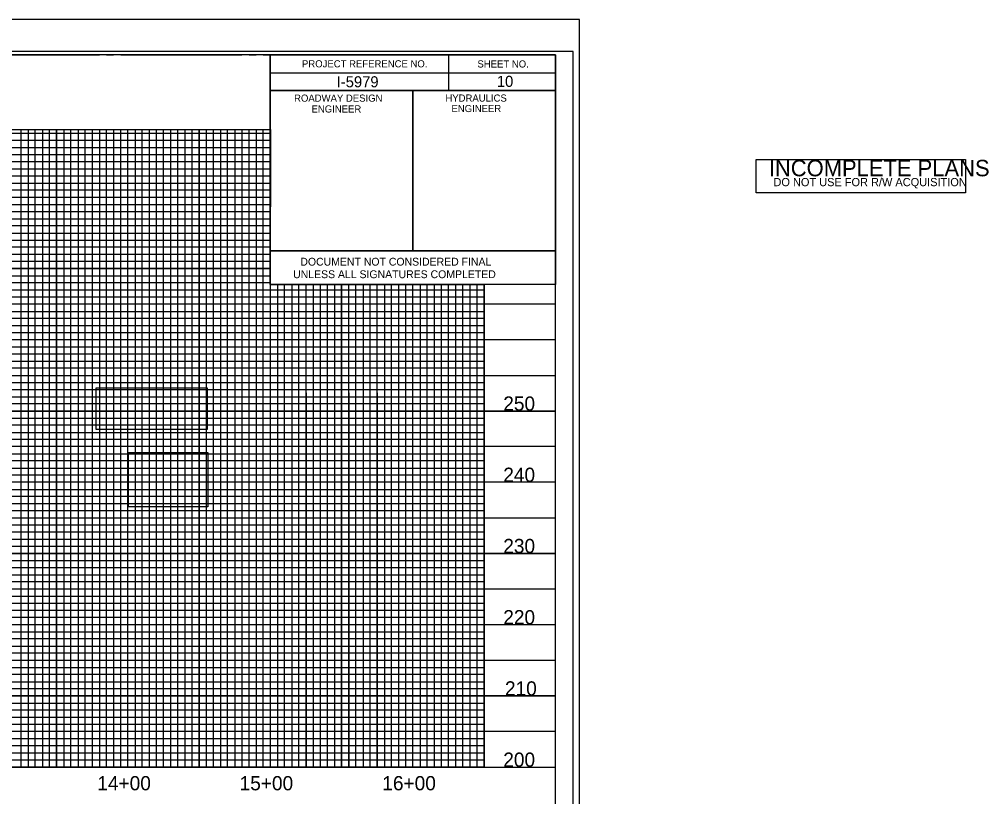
# Model space of a CAD drawing. Extents: x 1810963 to 1812934, y 722070 to 723170.
# Drawn here: x 1812254 to 1812934, y 722624 to 723170 of the extents above; entities that cross this region are included whole.
import ezdxf

# ---------------------------------------------------------------- set-up
doc = ezdxf.new("R2010")
doc.units = 0
for name, color, linetype in [('Old_Level_11', 7, 'Continuous'), ('Old_Level_2', 7, 'Continuous'), ('Prop Conc 2ft 6in Curb and Gutter', 7, 'Continuous'), ('Prop Dimension Text', 7, 'Continuous'), ('Prop Grid Mask', 7, 'Continuous'), ('Prop Horizontal Alignment Station Label', 7, 'Continuous'), ('Prop RDY Traffic Signal CELL', 7, 'Continuous'), ('Prop Shade Heavy', 7, 'Continuous'), ('Prop Shade Light', 7, 'Continuous'), ('Scratch_Level_0', 7, 'Continuous'), ('Scratch_Level_3', 7, 'Continuous'), ('Scratch_Level_5', 7, 'Continuous'), ('Sheet Block Title CELL', 7, 'Continuous'), ('Sheet North Arrow CELL', 7, 'Continuous'), ('Sheet Symbology CELL', 7, 'Continuous'), ('Sheet Title CELL', 7, 'Continuous')]:
    doc.layers.add(name, color=color, linetype=linetype)

msp = doc.modelspace()

# ---------------------------------------------------------------- linework, layer by layer
at = {"layer": 'Old_Level_11'}
msp.add_lwpolyline([(1810976.46, 722092.33), (1812642.96, 722092.33), (1812642.96, 723147.43), (1810976.46, 723147.43)], close=True, dxfattribs=at)
at = {"layer": 'Old_Level_2'}
for points in [[(1812308.11, 722911.09), (1812386.08, 722911.09), (1812386.08, 722881.84), (1812308.11, 722881.84)], [(1812330.97, 722865.77), (1812386.54, 722865.77), (1812386.54, 722827.65), (1812330.97, 722827.65)]]:
    msp.add_lwpolyline(points, close=True, dxfattribs=at)
at = {"layer": 'Prop Conc 2ft 6in Curb and Gutter'}
for p, q in [((1812280.46, 722644.88), (1812280.46, 723092.45)), ((1812330.46, 722644.88), (1812330.46, 723092.45)), ((1812380.46, 722644.88), (1812380.46, 723092.45)), ((1812430.41, 723044.88), (1811130.46, 723044.88)), ((1812430.46, 722644.88), (1812430.46, 723007.33)), ((1812430.46, 722994.88), (1811130.46, 722994.88)), ((1812480.46, 722644.88), (1812480.46, 722983.83)), ((1812530.46, 722644.88), (1812530.46, 722983.83)), ((1812580.46, 722644.88), (1812580.46, 722983.83)), ((1812630.46, 722944.88), (1811130.46, 722944.88)), ((1812630.46, 722894.88), (1811130.46, 722894.88)), ((1812630.46, 722844.88), (1811130.46, 722844.88)), ((1812630.46, 722794.88), (1811130.46, 722794.88)), ((1812630.46, 722744.88), (1811130.46, 722744.88)), ((1812630.46, 722694.88), (1811130.46, 722694.88))]:
    msp.add_line(p, q, dxfattribs=at)
at = {"layer": 'Prop Dimension Text'}
for p, q in [((1812430.41, 722983.83), (1812430.41, 723007.33)), ((1812430.41, 723007.33), (1812630.45, 723007.33)), ((1812430.41, 722983.83), (1812430.41, 723007.33)), ((1812430.41, 723007.33), (1812630.45, 723007.33)), ((1812630.45, 723007.32), (1812630.45, 722983.82)), ((1812630.45, 723007.32), (1812630.45, 722983.82)), ((1812630.45, 722983.83), (1812430.41, 722983.83)), ((1812630.45, 722983.83), (1812430.41, 722983.83))]:
    msp.add_line(p, q, dxfattribs=at)
at = {"layer": 'Prop Horizontal Alignment Station Label'}
msp.add_lwpolyline([(1812771.3, 723048.01), (1812771.3, 723071.51), (1812918.3, 723071.51), (1812918.3, 723048.01)], close=True, dxfattribs=at)
at = {"layer": 'Prop RDY Traffic Signal CELL'}
msp.add_line((1812647.46, 723169.88), (1810963.46, 723169.88), dxfattribs=at)
at = {"layer": 'Prop Shade Heavy'}
for points in [[(1812230.46, 723144.88), (1812280.46, 723144.88)], [(1812330.46, 723144.88), (1812380.46, 723144.88)], [(1812380.46, 723092.45), (1812380.46, 722644.88), (1812430.46, 722644.88), (1812430.46, 723144.88), (1812456.76, 723144.88)], [(1812280.46, 723092.45), (1812280.46, 722644.88), (1812330.46, 722644.88), (1812330.46, 723092.45)], [(1812430.46, 723044.88), (1811130.46, 723044.88), (1811130.46, 722994.88), (1812430.46, 722994.88)], [(1812580.46, 722983.83), (1812580.46, 722644.88), (1812630.46, 722644.88), (1812630.46, 722994.88)], [(1812480.46, 722983.83), (1812480.46, 722644.88), (1812530.46, 722644.88), (1812530.46, 722644.88), (1812530.46, 722983.83)], [(1812630.46, 722944.88), (1811130.46, 722944.88), (1811130.46, 722894.88), (1812630.46, 722894.88)], [(1812630.46, 722844.88), (1811130.46, 722844.88), (1811130.46, 722794.88), (1812630.46, 722794.88)], [(1812630.46, 722744.88), (1811130.46, 722744.88), (1811130.46, 722744.88), (1811130.46, 722694.88), (1812630.46, 722694.88)]]:
    msp.add_lwpolyline(points, dxfattribs=at)
at = {"layer": 'Prop Shade Light'}
for p, q in [((1812255.46, 723144.88), (1812305.46, 723144.88)), ((1812355.46, 723144.88), (1812405.46, 723144.88)), ((1812255.46, 722644.88), (1812255.46, 723092.45)), ((1812305.46, 723092.45), (1812305.46, 722644.88)), ((1812355.46, 722644.88), (1812355.46, 723092.45)), ((1812405.46, 723092.45), (1812405.46, 722644.88)), ((1812455.46, 722644.88), (1812455.46, 722983.83)), ((1812205.46, 722644.88), (1812255.46, 722644.88)), ((1812305.46, 722644.88), (1812355.46, 722644.88)), ((1812405.46, 722644.88), (1812455.46, 722644.88))]:
    msp.add_line(p, q, dxfattribs=at)
for points in [[(1812430.46, 723069.88), (1811130.46, 723069.88), (1811130.46, 723019.88), (1812430.46, 723019.88)], [(1812455.46, 722907.68), (1812455.46, 722644.88), (1812505.46, 722644.88), (1812505.46, 722983.83)], [(1812505.46, 722907.68), (1812505.46, 722644.88), (1812555.46, 722644.88), (1812555.46, 722983.83)], [(1812630.46, 722969.88), (1811130.46, 722969.88), (1811130.46, 722919.88), (1812455.46, 722919.88)], [(1812455.46, 722919.88), (1812630.46, 722919.88)], [(1812630.46, 722869.88), (1811130.46, 722869.88), (1811130.46, 722819.88), (1812630.46, 722819.88)], [(1812630.46, 722769.88), (1811130.46, 722769.88), (1811130.46, 722719.88), (1812630.46, 722719.88)], [(1812630.46, 722669.88), (1811130.46, 722669.88)]]:
    msp.add_lwpolyline(points, dxfattribs=at)
at = {"layer": 'Scratch_Level_3'}
msp.add_lwpolyline([(1811180.46, 723144.88), (1812230.46, 723144.88), (1812230.46, 723092.45), (1812430.5, 723092.45), (1812430.41, 722983.83), (1812580.46, 722983.83), (1812580.46, 722644.88), (1811180.46, 722644.88)], close=True, dxfattribs=at)
at = {"layer": 'Scratch_Level_5'}
msp.add_lwpolyline([(1811180.46, 722983.83), (1811180.46, 722644.88), (1812580.46, 722644.88), (1812580.46, 722983.83)], dxfattribs=at)
at = {"layer": 'Sheet North Arrow CELL'}
msp.add_lwpolyline([(1810963.46, 722069.88), (1812647.46, 722069.88), (1812647.46, 723169.88), (1810963.46, 723169.88)], close=True, dxfattribs=at)
at = {"layer": 'Sheet Symbology CELL'}
for p, q in [((1812555.46, 723144.83), (1812555.46, 723119.83)), ((1812430.41, 723132.33), (1812630.46, 723132.33)), ((1812530.46, 723119.83), (1812530.46, 723007.38)), ((1811130.46, 722644.88), (1812630.46, 722644.88))]:
    msp.add_line(p, q, dxfattribs=at)
for points in [[(1812630.46, 723144.88), (1811130.46, 723144.88), (1811130.46, 722094.88), (1812630.46, 722094.88)], [(1812430.41, 723144.88), (1812630.46, 723144.88), (1812630.46, 723119.83), (1812430.41, 723119.83)], [(1812430.41, 723119.83), (1812530.46, 723119.83), (1812530.46, 723007.33), (1812430.41, 723007.33)], [(1812530.46, 723119.83), (1812630.46, 723119.83), (1812630.46, 723007.33), (1812530.46, 723007.33)]]:
    msp.add_lwpolyline(points, close=True, dxfattribs=at)
at = {"layer": 'Sheet Title CELL'}
for p, q in [((1812250.46, 723144.88), (1812260.46, 723144.88)), ((1812265.46, 723144.88), (1812270.46, 723144.88)), ((1812275.46, 723144.88), (1812285.46, 723144.88)), ((1812290.46, 723144.88), (1812295.46, 723144.88)), ((1812300.46, 723144.88), (1812310.46, 723144.88)), ((1812315.46, 723144.88), (1812320.46, 723144.88)), ((1811180.46, 723089.88), (1812430.46, 723089.88)), ((1812260.46, 723092.45), (1812260.46, 722644.88)), ((1812265.46, 722644.88), (1812265.46, 723092.45)), ((1812270.46, 723092.45), (1812270.46, 722644.88)), ((1812275.46, 722644.88), (1812275.46, 723092.45)), ((1812285.46, 723092.45), (1812285.46, 722644.88)), ((1812290.46, 722644.88), (1812290.46, 723092.45)), ((1812295.46, 723092.45), (1812295.46, 722644.88)), ((1812300.46, 722644.88), (1812300.46, 723092.45)), ((1812310.46, 723092.45), (1812310.46, 722644.88)), ((1812315.46, 722644.88), (1812315.46, 723092.45)), ((1812320.46, 723092.45), (1812320.46, 722644.88)), ((1812430.41, 723009.88), (1811180.46, 723009.88)), ((1812430.46, 723004.88), (1811180.46, 723004.88)), ((1812430.46, 722999.88), (1811180.46, 722999.88)), ((1811180.46, 722989.88), (1812430.46, 722989.88)), ((1812430.46, 722984.88), (1811180.46, 722984.88)), ((1811180.46, 722979.88), (1812580.46, 722979.88)), ((1812580.46, 722959.88), (1811180.46, 722959.88)), ((1811180.46, 722954.88), (1812580.46, 722954.88)), ((1812580.46, 722934.88), (1811180.46, 722934.88)), ((1811180.46, 722929.88), (1812580.46, 722929.88)), ((1812580.46, 722909.88), (1811180.46, 722909.88)), ((1811180.46, 722904.88), (1812580.46, 722904.88)), ((1812580.46, 722899.88), (1811180.46, 722899.88)), ((1811180.46, 722889.88), (1812580.46, 722889.88)), ((1812580.46, 722884.88), (1811180.46, 722884.88)), ((1811180.46, 722879.88), (1812580.46, 722879.88)), ((1812580.46, 722874.88), (1811180.46, 722874.88)), ((1811180.46, 722864.88), (1812580.46, 722864.88)), ((1812580.46, 722859.88), (1811180.46, 722859.88)), ((1811180.46, 722854.88), (1812580.46, 722854.88)), ((1812580.46, 722849.88), (1811180.46, 722849.88)), ((1811180.46, 722839.88), (1812580.46, 722839.88)), ((1812580.46, 722834.88), (1811180.46, 722834.88)), ((1811180.46, 722829.88), (1812580.46, 722829.88)), ((1812580.46, 722824.88), (1811180.46, 722824.88)), ((1811180.46, 722814.88), (1812580.46, 722814.88)), ((1812580.46, 722809.88), (1811180.46, 722809.88)), ((1811180.46, 722804.88), (1812580.46, 722804.88)), ((1812580.46, 722799.88), (1811180.46, 722799.88)), ((1811180.46, 722789.88), (1812580.46, 722789.88)), ((1812580.46, 722784.88), (1811180.46, 722784.88)), ((1811180.46, 722779.88), (1812580.46, 722779.88)), ((1812580.46, 722774.88), (1811180.46, 722774.88)), ((1811180.46, 722764.88), (1812580.46, 722764.88)), ((1812580.46, 722759.88), (1811180.46, 722759.88)), ((1812580.46, 722754.88), (1811180.46, 722754.88)), ((1812580.46, 722749.88), (1811180.46, 722749.88)), ((1811180.46, 722739.88), (1812580.46, 722739.88)), ((1812580.46, 722734.88), (1811180.46, 722734.88)), ((1811180.46, 722729.88), (1812580.46, 722729.88)), ((1812580.46, 722724.88), (1811180.46, 722724.88)), ((1811180.46, 722714.88), (1812580.46, 722714.88)), ((1812580.46, 722709.88), (1811180.46, 722709.88)), ((1811180.46, 722704.88), (1812580.46, 722704.88)), ((1812580.46, 722699.88), (1811180.46, 722699.88)), ((1811180.46, 722689.88), (1812580.46, 722689.88)), ((1812580.46, 722684.88), (1811180.46, 722684.88)), ((1811180.46, 722679.88), (1812580.46, 722679.88)), ((1812580.46, 722674.88), (1811180.46, 722674.88)), ((1811180.46, 722664.88), (1812580.46, 722664.88)), ((1812580.46, 722659.88), (1811180.46, 722659.88)), ((1811180.46, 722654.88), (1812580.46, 722654.88)), ((1812260.46, 722644.88), (1812265.46, 722644.88)), ((1812270.46, 722644.88), (1812275.46, 722644.88)), ((1812285.46, 722644.88), (1812290.46, 722644.88)), ((1812295.46, 722644.88), (1812300.46, 722644.88)), ((1812310.46, 722644.88), (1812315.46, 722644.88))]:
    msp.add_line(p, q, dxfattribs=at)
for points in [[(1812325.46, 723144.88), (1812335.46, 723144.88)], [(1812340.46, 723144.88), (1812345.46, 723144.88)], [(1812350.46, 723144.88), (1812360.46, 723144.88)], [(1812365.46, 723144.88), (1812370.46, 723144.88)], [(1812375.46, 723144.88), (1812385.46, 723144.88)], [(1812390.46, 723144.88), (1812395.46, 723144.88)], [(1812400.46, 723144.88), (1812410.46, 723144.88)], [(1812415.46, 723144.88), (1812420.46, 723144.88)], [(1812425.46, 723144.88), (1812435.46, 723144.88)], [(1812320.46, 722644.88), (1812325.46, 722644.88), (1812325.46, 723092.45)], [(1812335.46, 723092.45), (1812335.46, 722644.88), (1812340.46, 722644.88), (1812340.46, 723092.45)], [(1812345.46, 723092.45), (1812345.46, 722644.88), (1812350.46, 722644.88), (1812350.46, 723092.45)], [(1812360.46, 723092.45), (1812360.46, 722644.88), (1812365.46, 722644.88), (1812365.46, 723092.45)], [(1812370.46, 723092.45), (1812370.46, 722644.88), (1812375.46, 722644.88), (1812375.46, 723092.45)], [(1812385.46, 723092.45), (1812385.46, 722644.88), (1812390.46, 722644.88), (1812390.46, 723092.45)], [(1812395.46, 723092.45), (1812395.46, 722644.88), (1812400.46, 722644.88), (1812400.46, 723092.45)], [(1812410.46, 723092.45), (1812410.46, 722644.88), (1812415.46, 722644.88), (1812415.46, 723092.45)], [(1812420.46, 723092.45), (1812420.46, 722644.88), (1812425.46, 722644.88), (1812425.46, 723092.45)], [(1812430.46, 723084.88), (1811180.46, 723084.88), (1811180.46, 723079.88), (1812430.46, 723079.88)], [(1812430.46, 723074.88), (1811180.46, 723074.88), (1811180.46, 723064.88), (1812430.46, 723064.88)], [(1812430.46, 723059.88), (1811180.46, 723059.88), (1811180.46, 723054.88), (1812430.46, 723054.88)], [(1812430.46, 723049.88), (1811180.46, 723049.88), (1811180.46, 723039.88), (1812430.46, 723039.88)], [(1812430.46, 723034.78), (1811180.56, 723034.78), (1811180.56, 723029.88), (1812430.46, 723029.88)], [(1812430.46, 723024.88), (1811180.46, 723024.88), (1811180.46, 723014.88), (1812430.46, 723014.88)], [(1812435.46, 722983.83), (1812435.46, 722644.88), (1812440.46, 722644.88), (1812440.46, 722983.83)], [(1812445.46, 722983.83), (1812445.46, 722644.88), (1812450.46, 722644.88), (1812450.46, 722983.83)], [(1812460.46, 722983.83), (1812460.46, 722644.88), (1812460.46, 722644.88), (1812465.46, 722644.88), (1812470.46, 722644.88), (1812470.46, 722983.83)], [(1812465.46, 722983.83), (1812465.46, 722644.88)], [(1812475.45, 722983.83), (1812475.36, 722644.93), (1812480.36, 722644.93), (1812485.46, 722644.88), (1812485.46, 722983.83)], [(1812485.46, 722907.68), (1812485.46, 722644.88), (1812490.46, 722644.88), (1812490.46, 722983.83)], [(1812495.46, 722983.83), (1812495.46, 722644.88), (1812500.46, 722644.88), (1812500.46, 722983.83)], [(1812510.46, 722983.83), (1812510.46, 722644.88), (1812515.46, 722644.88), (1812515.46, 722983.83)], [(1812520.46, 722983.83), (1812520.46, 722644.88), (1812525.46, 722644.88), (1812525.46, 722983.83)], [(1812535.46, 722983.83), (1812535.46, 722644.88), (1812540.46, 722644.88), (1812540.46, 722983.83)], [(1812545.46, 722983.83), (1812545.46, 722644.88), (1812550.46, 722644.88), (1812550.46, 722983.83)], [(1812560.46, 722983.83), (1812560.46, 722644.88), (1812565.46, 722644.88), (1812565.46, 722983.83)], [(1812570.46, 722983.83), (1812570.46, 722644.88), (1812575.46, 722644.88), (1812575.46, 722983.83)], [(1812580.46, 722974.88), (1811180.46, 722974.88), (1811180.46, 722964.88), (1812580.46, 722964.88)], [(1812580.46, 722949.88), (1811180.46, 722949.88), (1811180.46, 722939.88), (1812580.46, 722939.88)], [(1812580.46, 722924.88), (1811180.46, 722924.88), (1811180.46, 722914.88), (1812580.46, 722914.88)], [(1812580.46, 722649.88), (1811180.46, 722649.88)]]:
    msp.add_lwpolyline(points, dxfattribs=at)

# ---------------------------------------------------------------- texts
at = {"layer": 'Prop Dimension Text'}
for s, p in [('DOCUMENT NOT CONSIDERED FINAL', (1812451.48, 722996.99)), ('DOCUMENT NOT CONSIDERED FINAL', (1812451.48, 722996.99)), ('UNLESS ALL SIGNATURES COMPLETED', (1812446.41, 722988.19)), ('UNLESS ALL SIGNATURES COMPLETED', (1812446.41, 722988.19))]:
    msp.add_text(s, height=5.5, dxfattribs=at).set_placement(p)
at = {"layer": 'Prop Grid Mask'}
for s, p in [('I-5979', (1812476.99, 723122.19)), ('10', (1812589.38, 723122.49))]:
    msp.add_text(s, height=7.75, dxfattribs=at).set_placement(p)
at = {"layer": 'Prop Horizontal Alignment Station Label'}
for s, height, p in [('INCOMPLETE PLANS', 11.52, (1812780.25, 723059.71)), ('DO NOT USE FOR R/W ACQUISITION', 5.76, (1812783.5, 723052.76))]:
    msp.add_text(s, height=height, dxfattribs=at).set_placement(p)
at = {"layer": 'Scratch_Level_0'}
for s, p in [('250', (1812593.89, 722895.13)), ('240', (1812593.89, 722845.13)), ('230', (1812593.89, 722795.13)), ('220', (1812593.89, 722745.13)), ('210', (1812595.09, 722695.13)), ('200', (1812593.89, 722645.13))]:
    msp.add_text(s, height=10, dxfattribs=at).set_placement(p)
at = {"layer": 'Sheet Block Title CELL'}
for s, p in [('14+00', (1812309.01, 722628.6)), ('15+00', (1812408.88, 722628.6)), ('16+00', (1812509.01, 722628.6))]:
    msp.add_text(s, height=10, dxfattribs=at).set_placement(p)
at = {"layer": 'Sheet Symbology CELL'}
for s, height, p in [('PROJECT REFERENCE NO.', 5.0001, (1812452.62, 723136.19)), ('SHEET NO.', 5, (1812575.77, 723136.09)), ('ROADWAY DESIGN', 5.0001, (1812447.07, 723112.09)), ('HYDRAULICS', 5, (1812553.27, 723112.14)), ('ENGINEER', 5, (1812459.32, 723104.49)), ('ENGINEER', 5, (1812557.52, 723104.79))]:
    msp.add_text(s, height=height, dxfattribs=at).set_placement(p)

doc.saveas('drawing.dxf')
